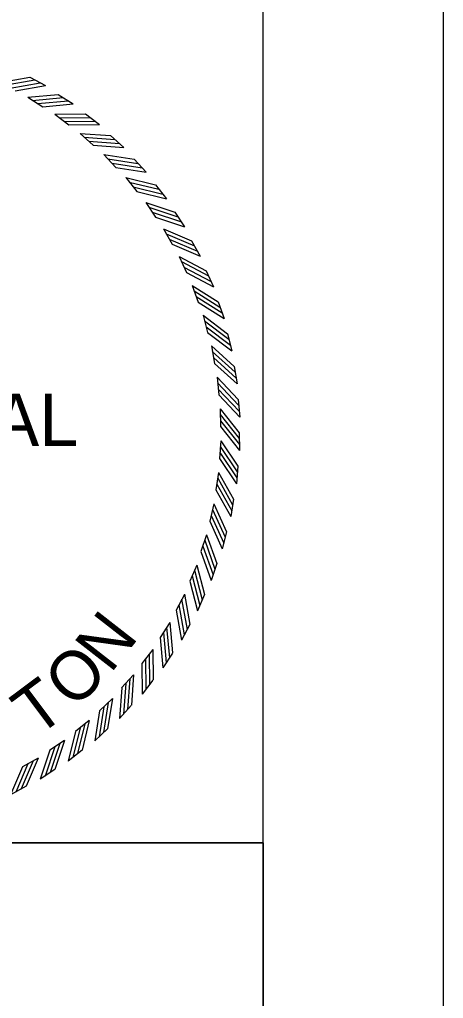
# Model space of a CAD drawing. Extents: x 0 to 1228740, y 0 to 152440.
# Drawn here: x 32.645 to 34, y 17.279 to 20.411 of the extents above; entities that cross this region are included whole.
import ezdxf

# ---------------------------------------------------------------- set-up
doc = ezdxf.new("R2010")
doc.units = 0
for name, color, linetype in [('R_Border', 7, 'Continuous'), ('R_No Plot', 7, 'Continuous'), ('STAMP_TNC', 7, 'Continuous')]:
    doc.layers.add(name, color=color, linetype=linetype)

msp = doc.modelspace()

# ---------------------------------------------------------------- linework, layer by layer
at = {"layer": 'R_Border'}
msp.add_line((33.4231, 0.5768), (33.4231, 21.4232), dxfattribs=at)
msp.add_lwpolyline([(33.9999, 22), (-0.0001, 22), (-0.0001, 0), (33.9999, 0)], close=True, dxfattribs=at)
at = {"layer": 'R_No Plot'}
msp.add_lwpolyline([(27.1591, 21.4232), (1.516, 21.4232), (1.516, 10.8708), (33.4231, 10.8708), (33.4231, 17.7768), (30.6665, 17.7768), (30.6665, 19.4815), (28.8871, 19.4815), (28.8871, 20.4352), (27.1591, 20.4352)], close=True, dxfattribs=at)
for points in [[(33.4231, 17.7768), (33.4231, 0.5768), (1.516, 0.5768), (1.516, 21.4232), (27.1591, 21.4232), (27.1591, 20.4352), (28.8871, 20.4352), (28.8871, 19.4815), (30.6665, 19.4815)], [(30.6665, 19.4815), (30.6665, 17.7768), (33.4231, 17.7768)]]:
    msp.add_lwpolyline(points, dxfattribs=at)
at = {"layer": 'STAMP_TNC'}
for p, q in [((32.6771, 20.2262), (32.7271, 20.1998)), ((32.7684, 20.1712), (32.8161, 20.1407)), ((32.671, 20.1621), (32.7187, 20.1315)), ((32.757, 20.1078), (32.8021, 20.0734)), ((32.8549, 20.1088), (32.8998, 20.0745)), ((32.8383, 20.0466), (32.8803, 20.0086)), ((32.9359, 20.0395), (32.9778, 20.0016)), ((32.9142, 19.9789), (32.9529, 19.9375)), ((33.0109, 19.9637), (33.0495, 19.9225)), ((32.9842, 19.9051), (33.0195, 19.8607)), ((33.0793, 19.882), (33.1145, 19.8377)), ((33.048, 19.8258), (33.0794, 19.7786)), ((33.1408, 19.795), (33.1722, 19.7479)), ((33.1049, 19.7415), (33.1324, 19.6919)), ((33.1949, 19.7031), (33.2223, 19.6536)), ((33.1547, 19.6528), (33.178, 19.6011)), ((33.2413, 19.6071), (33.2644, 19.5555)), ((33.197, 19.5603), (33.2159, 19.5069)), ((33.2795, 19.5076), (33.2984, 19.4543)), ((33.2316, 19.4646), (33.246, 19.4098)), ((33.3094, 19.4053), (33.3238, 19.3506)), ((33.2581, 19.3664), (33.2679, 19.3106)), ((33.3307, 19.3009), (33.3406, 19.2452)), ((33.2764, 19.2663), (33.2816, 19.2099)), ((33.3434, 19.195), (33.3486, 19.1387)), ((33.2864, 19.1651), (33.2869, 19.1084)), ((33.3472, 19.0885), (33.3478, 19.0319)), ((33.2879, 19.0634), (33.2838, 19.0068)), ((33.3423, 18.982), (33.3381, 18.9256)), ((33.2811, 18.9619), (33.2723, 18.9059)), ((33.2659, 18.8613), (33.2525, 18.8062)), ((33.3286, 18.8763), (33.3198, 18.8204)), ((33.2425, 18.7623), (33.2246, 18.7085)), ((33.3062, 18.7721), (33.2928, 18.7171)), ((33.211, 18.6656), (33.1887, 18.6135)), ((33.2752, 18.6701), (33.2574, 18.6164)), ((33.1716, 18.5718), (33.1451, 18.5217)), ((33.236, 18.571), (33.2137, 18.519)), ((33.1246, 18.4816), (33.094, 18.4338)), ((33.1887, 18.4754), (33.1622, 18.4254)), ((33.0703, 18.3956), (33.0359, 18.3505)), ((33.1336, 18.3841), (33.1031, 18.3365)), ((33.009, 18.3143), (32.971, 18.2723)), ((33.0712, 18.2977), (33.0369, 18.2528)), ((32.9413, 18.2384), (32.9, 18.1996)), ((33.0019, 18.2167), (32.964, 18.1748)), ((32.8676, 18.1683), (32.8231, 18.1331)), ((32.9262, 18.1417), (32.8849, 18.103)), ((32.7883, 18.1046), (32.7411, 18.0732)), ((32.8445, 18.0732), (32.8002, 18.0381)), ((32.704, 18.0477), (32.6544, 18.0202)), ((32.7574, 18.0117), (32.7104, 17.9804)), ((32.6656, 17.9576), (32.6161, 17.9303))]:
    msp.add_line(p, q, dxfattribs=at)
for points in [[(32.5807, 20.2091), (32.677, 20.2262)], [(32.5967, 20.2005), (32.6931, 20.2175)], [(32.6143, 20.1916), (32.7106, 20.2087)], [(32.6308, 20.1827), (32.7272, 20.1998)], [(32.6709, 20.1621), (32.7683, 20.1712)], [(32.6862, 20.1521), (32.7836, 20.1612)], [(32.7029, 20.1419), (32.8004, 20.151)], [(32.7187, 20.1316), (32.8161, 20.1407)], [(32.7569, 20.1078), (32.8548, 20.1088)], [(32.7713, 20.0966), (32.8691, 20.0976)], [(32.7872, 20.085), (32.885, 20.086)], [(32.802, 20.0735), (32.8999, 20.0745)], [(32.8382, 20.0466), (32.9358, 20.0395)], [(32.8516, 20.0343), (32.9492, 20.0272)], [(32.8664, 20.0214), (32.964, 20.0143)], [(32.8803, 20.0087), (32.9779, 20.0016)], [(32.9141, 19.9789), (33.0108, 19.9638)], [(32.9264, 19.9655), (33.0231, 19.9504)], [(32.9402, 19.9514), (33.0368, 19.9363)], [(32.9529, 19.9376), (33.0496, 19.9225)], [(32.9841, 19.9051), (33.0792, 19.8821)], [(32.9953, 19.8908), (33.0904, 19.8677)], [(33.0079, 19.8756), (33.103, 19.8526)], [(33.0194, 19.8608), (33.1145, 19.8377)], [(33.0479, 19.8258), (33.1407, 19.795)], [(33.0578, 19.8106), (33.1507, 19.7798)], [(33.0691, 19.7945), (33.162, 19.7637)], [(33.0794, 19.7787), (33.1723, 19.7479)], [(33.1048, 19.7416), (33.1948, 19.7032)], [(33.1135, 19.7255), (33.2035, 19.6872)], [(33.1234, 19.7086), (33.2134, 19.6702)], [(33.1324, 19.692), (33.2224, 19.6536)], [(33.1547, 19.6529), (33.2412, 19.6072)], [(33.162, 19.6362), (33.2485, 19.5905)], [(33.1704, 19.6184), (33.2569, 19.5728)], [(33.178, 19.6012), (33.2645, 19.5555)], [(33.197, 19.5603), (33.2794, 19.5077)], [(33.2029, 19.5431), (33.2853, 19.4905)], [(33.2098, 19.5248), (33.2923, 19.4721)], [(33.216, 19.5069), (33.2984, 19.4543)], [(33.2315, 19.4647), (33.3093, 19.4054)], [(33.236, 19.447), (33.3138, 19.3877)], [(33.2414, 19.4281), (33.3192, 19.3688)], [(33.246, 19.4099), (33.3238, 19.3506)], [(33.258, 19.3665), (33.3307, 19.3009)], [(33.261, 19.3485), (33.3337, 19.283)], [(33.2648, 19.3292), (33.3375, 19.2637)], [(33.2679, 19.3107), (33.3406, 19.2451)], [(33.2763, 19.2664), (33.3433, 19.1951)], [(33.2778, 19.2483), (33.3448, 19.1769)], [(33.2801, 19.2287), (33.3471, 19.1574)], [(33.2816, 19.21), (33.3486, 19.1386)], [(33.2863, 19.1652), (33.3472, 19.0886)], [(33.2863, 19.147), (33.3472, 19.0704)], [(33.2869, 19.1273), (33.3478, 19.0507)], [(33.2869, 19.1085), (33.3478, 19.0319)], [(33.2864, 19.0453), (33.3407, 18.9639)], [(33.2879, 19.0634), (33.3422, 18.9821)], [(33.2854, 19.0257), (33.3397, 18.9443)], [(33.2838, 19.0069), (33.3382, 18.9255)], [(33.2811, 18.9619), (33.3285, 18.8764)], [(33.2755, 18.9245), (33.3229, 18.8389)], [(33.2781, 18.944), (33.3255, 18.8584)], [(33.2724, 18.9059), (33.3198, 18.8204)], [(33.2659, 18.8614), (33.3061, 18.7722)], [(33.2572, 18.8245), (33.2974, 18.7353)], [(33.2614, 18.8437), (33.3017, 18.7545)], [(33.2526, 18.8063), (33.2928, 18.7171)], [(33.2425, 18.7624), (33.2752, 18.6702)], [(33.2366, 18.7452), (33.2693, 18.6529)], [(33.2247, 18.7086), (33.2574, 18.6163)], [(33.2308, 18.7264), (33.2635, 18.6342)], [(33.211, 18.6657), (33.236, 18.571)], [(33.2037, 18.649), (33.2286, 18.5544)], [(33.1888, 18.6135), (33.2137, 18.5189)], [(33.1963, 18.6308), (33.2213, 18.5361)], [(33.1716, 18.5719), (33.1887, 18.4755)], [(33.1629, 18.5559), (33.18, 18.4595)], [(33.1451, 18.5217), (33.1622, 18.4254)], [(33.1541, 18.5383), (33.1712, 18.442)], [(33.1246, 18.4817), (33.1336, 18.3842)], [(33.1044, 18.4496), (33.1134, 18.3522)], [(33.1146, 18.4664), (33.1237, 18.369)], [(33.0941, 18.4339), (33.1031, 18.3364)], [(33.0703, 18.3956), (33.0713, 18.2978)], [(33.0475, 18.3654), (33.0485, 18.2676)], [(33.0591, 18.3813), (33.0601, 18.2834)], [(33.0359, 18.3505), (33.0369, 18.2527)], [(32.9967, 18.301), (32.9896, 18.2034)], [(33.009, 18.3144), (33.002, 18.2168)], [(32.9711, 18.2723), (32.964, 18.1747)], [(32.9839, 18.2861), (32.9768, 18.1885)], [(32.9279, 18.2262), (32.9128, 18.1295)], [(32.9413, 18.2385), (32.9262, 18.1418)], [(32.9, 18.1996), (32.8849, 18.103)], [(32.9139, 18.2124), (32.8988, 18.1157)], [(32.8676, 18.1684), (32.8445, 18.0733)], [(32.8232, 18.1331), (32.8002, 18.038)], [(32.8381, 18.1447), (32.815, 18.0496)], [(32.8532, 18.1572), (32.8302, 18.0622)], [(32.7883, 18.1047), (32.7575, 18.0118)], [(32.7412, 18.0732), (32.7103, 17.9803)], [(32.7569, 18.0835), (32.7261, 17.9906)], [(32.773, 18.0947), (32.7422, 18.0019)], [(32.688, 18.0391), (32.6496, 17.9491)], [(32.704, 18.0477), (32.6656, 17.9577)], [(32.6544, 18.0202), (32.6161, 17.9302)], [(32.671, 18.0292), (32.6326, 17.9392)]]:
    msp.add_lwpolyline(points, dxfattribs=at)

# ---------------------------------------------------------------- texts
msp.add_text('PROFESSIONAL', height=0.167907, dxfattribs=at).set_placement((31.0857, 19.0459))
for s, rotation, p in [('N', 52.0417, (32.9354, 18.3159)), ('O', 44.0353, (32.8183, 18.2012)), ('T', 36.7567, (32.6989, 18.112))]:
    msp.add_text(s, height=0.1562, rotation=rotation, dxfattribs=at).set_placement(p)

doc.saveas('drawing.dxf')
